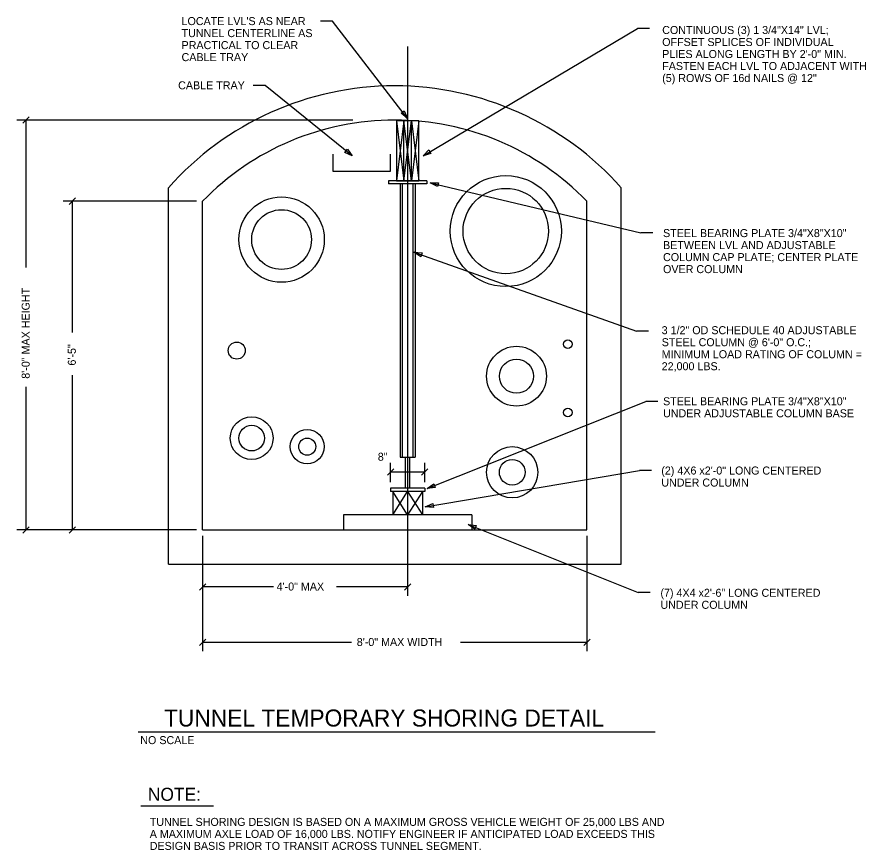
# Model space of a CAD drawing. Extents: x 10051 to 10282, y 10006 to 10178.
# Drawn here: x 10051.3 to 10122, y 10108.7 to 10178.1 of the extents above; entities that cross this region are included whole.
import ezdxf

# ---------------------------------------------------------------- set-up
doc = ezdxf.new("R2010")
doc.units = 0
for name, color, linetype in [('G-ANNO-CELL', 7, 'Continuous'), ('G-ANNO-TEXT', 7, 'Continuous'), ('G-DETL-LINE', 7, 'Continuous')]:
    doc.layers.add(name, color=color, linetype=linetype)

msp = doc.modelspace()

# ---------------------------------------------------------------- linework, layer by layer
at = {"layer": 'G-ANNO-CELL'}
for p, q in [((10061.376, 10118.596), (10104.41, 10118.596)), ((10061.601, 10112.409), (10067.647, 10112.409))]:
    msp.add_line(p, q, dxfattribs=at)
at = {"layer": 'G-ANNO-TEXT'}
for p, q in [((10077.569, 10177.77), (10076.569, 10177.77)), ((10083.801, 10169.673), (10077.569, 10177.77)), ((10085.092, 10166.563), (10102.938, 10177.152)), ((10103.938, 10177.152), (10102.938, 10177.152)), ((10083.814, 10175.668), (10083.814, 10129.899)), ((10071.951, 10172.406), (10070.951, 10172.406)), ((10079.208, 10166.549), (10071.951, 10172.406)), ((10079.241, 10169.533), (10051.293, 10169.533)), ((10051.777, 10169.268), (10052.308, 10169.798)), ((10052.043, 10169.533), (10052.043, 10157.242)), ((10085.688, 10164.305), (10103.224, 10160.146)), ((10055.63, 10162.513), (10056.16, 10163.043)), ((10066.241, 10162.778), (10055.145, 10162.778)), ((10055.895, 10162.778), (10055.895, 10151.83)), ((10104.224, 10160.146), (10103.224, 10160.146)), ((10084.335, 10158.527), (10102.875, 10151.949)), ((10103.875, 10151.949), (10102.875, 10151.949)), ((10055.895, 10148.28), (10055.895, 10135.4)), ((10052.043, 10147.303), (10052.043, 10135.4)), ((10085.435, 10138.838), (10103.642, 10146.107)), ((10104.642, 10146.107), (10103.642, 10146.107)), ((10082.124, 10139.969), (10082.654, 10140.499)), ((10082.389, 10139.367), (10082.389, 10140.984)), ((10084.969, 10139.969), (10085.499, 10140.499)), ((10085.234, 10139.367), (10085.234, 10140.984)), ((10085.276, 10137.331), (10103.109, 10140.354)), ((10104.109, 10140.354), (10103.109, 10140.354)), ((10082.389, 10140.234), (10085.234, 10140.234)), ((10066.241, 10135.4), (10051.293, 10135.4)), ((10051.777, 10135.135), (10052.308, 10135.665)), ((10055.63, 10135.135), (10056.16, 10135.665)), ((10088.848, 10135.864), (10103.009, 10130.191)), ((10066.741, 10134.9), (10066.741, 10125.292)), ((10098.741, 10134.9), (10098.741, 10125.292)), ((10066.476, 10130.384), (10067.007, 10130.915)), ((10072.655, 10130.649), (10066.741, 10130.649)), ((10083.814, 10130.649), (10077.888, 10130.649)), ((10083.549, 10130.384), (10084.079, 10130.915)), ((10104.009, 10130.191), (10103.009, 10130.191)), ((10066.476, 10125.777), (10067.007, 10126.308)), ((10098.476, 10125.777), (10099.007, 10126.308)), ((10066.741, 10126.042), (10079.148, 10126.042)), ((10088.221, 10126.042), (10098.741, 10126.042))]:
    msp.add_line(p, q, dxfattribs=at)
for points in [[(10083.526, 10170.303), (10083.801, 10169.673), (10083.262, 10170.099)], [(10078.794, 10167.097), (10079.208, 10166.549), (10078.584, 10166.838)], [(10085.75, 10166.76), (10085.092, 10166.563), (10085.58, 10167.047)], [(10086.298, 10163.989), (10085.688, 10164.305), (10086.375, 10164.313)], [(10084.908, 10158.147), (10084.335, 10158.527), (10085.019, 10158.461)], [(10086.116, 10138.93), (10085.435, 10138.838), (10085.992, 10139.24)], [(10085.961, 10137.278), (10085.276, 10137.331), (10085.905, 10137.607)], [(10089.404, 10135.462), (10088.848, 10135.864), (10089.528, 10135.771)]]:
    msp.add_lwpolyline(points, close=True, dxfattribs=at)
at = {"layer": 'G-DETL-LINE'}
for p, q in [((10082.88, 10169.46), (10082.88, 10164.482)), ((10083.503, 10169.46), (10082.88, 10169.46)), ((10082.88, 10169.46), (10083.503, 10164.482)), ((10083.503, 10169.46), (10082.88, 10164.482)), ((10083.503, 10164.482), (10083.503, 10169.46)), ((10084.125, 10169.46), (10083.503, 10169.46)), ((10083.503, 10164.482), (10084.125, 10169.46)), ((10084.125, 10164.482), (10083.503, 10169.46)), ((10084.125, 10164.482), (10084.125, 10169.46)), ((10084.747, 10169.46), (10084.125, 10169.46)), ((10084.125, 10169.46), (10084.747, 10164.482)), ((10084.747, 10169.46), (10084.125, 10164.482)), ((10084.747, 10164.482), (10084.747, 10169.46)), ((10077.586, 10166.689), (10077.586, 10165.267)), ((10082.386, 10165.267), (10082.386, 10166.689)), ((10077.586, 10165.267), (10082.386, 10165.267)), ((10085.414, 10164.482), (10082.214, 10164.482)), ((10082.214, 10164.482), (10082.214, 10164.216)), ((10082.88, 10164.482), (10083.503, 10164.482)), ((10083.503, 10164.482), (10084.125, 10164.482)), ((10084.125, 10164.482), (10084.747, 10164.482)), ((10085.414, 10164.482), (10085.414, 10164.216)), ((10063.897, 10132.555), (10063.897, 10163.893)), ((10085.414, 10164.216), (10082.214, 10164.216)), ((10083.192, 10164.216), (10083.192, 10141.454)), ((10083.369, 10164.216), (10083.369, 10141.454)), ((10084.258, 10164.216), (10084.258, 10141.454)), ((10084.436, 10164.216), (10084.436, 10141.454)), ((10101.586, 10132.555), (10101.586, 10163.893)), ((10066.741, 10135.4), (10066.741, 10162.778)), ((10098.741, 10135.4), (10098.741, 10162.778)), ((10083.192, 10141.454), (10084.436, 10141.454)), ((10083.634, 10138.867), (10083.634, 10141.454)), ((10083.989, 10138.867), (10083.989, 10141.454)), ((10085.234, 10138.867), (10082.389, 10138.867)), ((10082.389, 10138.867), (10082.389, 10138.6)), ((10085.234, 10138.6), (10082.389, 10138.6)), ((10082.567, 10138.6), (10082.567, 10136.644)), ((10082.567, 10136.644), (10083.812, 10138.6)), ((10083.812, 10136.644), (10082.567, 10138.6)), ((10083.812, 10138.6), (10083.812, 10136.644)), ((10083.812, 10138.6), (10085.056, 10136.644)), ((10085.056, 10138.6), (10083.812, 10136.644)), ((10085.056, 10138.6), (10085.056, 10136.644)), ((10085.234, 10138.867), (10085.234, 10138.6)), ((10083.189, 10136.644), (10078.478, 10136.644)), ((10078.478, 10136.644), (10078.478, 10135.4)), ((10084.434, 10136.644), (10083.189, 10136.644)), ((10089.145, 10136.644), (10084.434, 10136.644)), ((10089.145, 10136.644), (10089.145, 10135.4)), ((10066.741, 10135.4), (10098.741, 10135.4)), ((10078.478, 10135.4), (10083.189, 10135.4)), ((10083.189, 10135.4), (10084.434, 10135.4)), ((10084.434, 10135.4), (10089.145, 10135.4)), ((10063.897, 10132.555), (10101.586, 10132.555))]:
    msp.add_line(p, q, dxfattribs=at)
for centre, radius in [((10091.986, 10160.289), 4.622), ((10091.986, 10160.289), 3.556), ((10073.319, 10159.578), 3.556), ((10073.319, 10159.578), 2.489), ((10069.586, 10150.333), 0.711), ((10097.141, 10150.867), 0.356), ((10092.875, 10148.2), 2.489), ((10092.875, 10148.2), 1.422), ((10097.141, 10145.178), 0.356), ((10070.83, 10143.044), 1.778), ((10070.83, 10143.044), 1.067), ((10075.453, 10142.333), 1.422), ((10075.453, 10142.333), 0.711), ((10092.519, 10140.2), 2.133), ((10092.519, 10140.2), 1.067)]:
    msp.add_circle(centre, radius, dxfattribs=at)
for radius, start, end in [(25.17, 41.5222, 138.4778), (22.325, 44.2189, 135.7811)]:
    msp.add_arc((10082.741, 10147.208), radius, start, end, dxfattribs=at)

# ---------------------------------------------------------------- texts
at = {"layer": 'G-ANNO-CELL'}
for s, height, p in [('TUNNEL TEMPORARY SHORING DETAIL', 1.41667, (10063.533, 10119.028)), ('NO SCALE', 0.6667, (10061.557, 10117.561)), ('NOTE:', 1.0833, (10062.185, 10112.841))]:
    msp.add_text(s, height=height, dxfattribs=at).set_placement(p)
at = {"layer": 'G-ANNO-TEXT'}
for s, height, p in [("LOCATE LVL'S AS NEAR ", 0.66667, (10064.993, 10177.439)), ('TUNNEL CENTERLINE AS ', 0.66667, (10064.993, 10176.439)), ('CONTINUOUS (3) 1 3/4"X14" LVL; ', 0.66667, (10105.005, 10176.698)), ('OFFSET SPLICES OF INDIVIDUAL ', 0.66667, (10105.005, 10175.698)), ('PRACTICAL TO CLEAR ', 0.66667, (10064.993, 10175.439)), ('CABLE TRAY', 0.6667, (10064.993, 10174.439)), ('PLIES ALONG LENGTH BY 2\'-0" MIN. ', 0.66667, (10105.005, 10174.698)), ('FASTEN EACH LVL TO ADJACENT WITH ', 0.66667, (10105.005, 10173.698)), ('(5) ROWS OF 16d NAILS @ 12"', 0.66667, (10105.005, 10172.698)), ('CABLE TRAY', 0.6667, (10064.708, 10172.091)), ('STEEL BEARING PLATE 3/4"X8"X10" ', 0.66667, (10105.076, 10159.785)), ('BETWEEN LVL AND ADJUSTABLE ', 0.66667, (10105.076, 10158.785)), ('COLUMN CAP PLATE; CENTER PLATE ', 0.66667, (10105.076, 10157.785)), ('OVER COLUMN', 0.66667, (10105.076, 10156.785)), ('3 1/2" OD SCHEDULE 40 ADJUSTABLE ', 0.66667, (10104.962, 10151.698)), ('STEEL COLUMN @ 6\'-0" O.C.; ', 0.66667, (10104.962, 10150.698)), ('MINIMUM LOAD RATING OF COLUMN = ', 0.66667, (10104.962, 10149.698)), ('22,000 LBS.', 0.66667, (10104.962, 10148.698)), ('STEEL BEARING PLATE 3/4"X8"X10" ', 0.66667, (10105.076, 10145.779)), ('UNDER ADJUSTABLE COLUMN BASE', 0.66667, (10105.076, 10144.779)), ('8"', 0.6667, (10081.329, 10141.16)), ('(2) 4X6 x2\'-0" LONG CENTERED ', 0.66667, (10104.929, 10140.011)), ('UNDER COLUMN', 0.66667, (10104.929, 10139.011)), ('4\'-0" MAX', 0.6667, (10072.905, 10130.351)), ('(7) 4X4 x2\'-6" LONG CENTERED ', 0.66667, (10104.859, 10129.83)), ('UNDER COLUMN', 0.66667, (10104.859, 10128.83)), ('8\'-0" MAX WIDTH', 0.66667, (10079.579, 10125.732)), ('TUNNEL SHORING DESIGN IS BASED ON A MAXIMUM GROSS VEHICLE WEIGHT OF 25,000 LBS AND ', 0.66667, (10062.345, 10110.752)), ('A MAXIMUM AXLE LOAD OF 16,000 LBS. NOTIFY ENGINEER IF ANTICIPATED LOAD EXCEEDS THIS ', 0.66667, (10062.345, 10109.752)), ('DESIGN BASIS PRIOR TO TRANSIT ACROSS TUNNEL SEGMENT.', 0.66667, (10062.345, 10108.752))]:
    msp.add_text(s, height=height, dxfattribs=at).set_placement(p)
for s, height, p in [('8\'-0" MAX HEIGHT', 0.66667, (10052.348, 10147.99)), ('6\'-5" ', 0.6667, (10056.19, 10149.087))]:
    msp.add_text(s, height=height, rotation=90, dxfattribs=at).set_placement(p)

doc.saveas('drawing.dxf')
